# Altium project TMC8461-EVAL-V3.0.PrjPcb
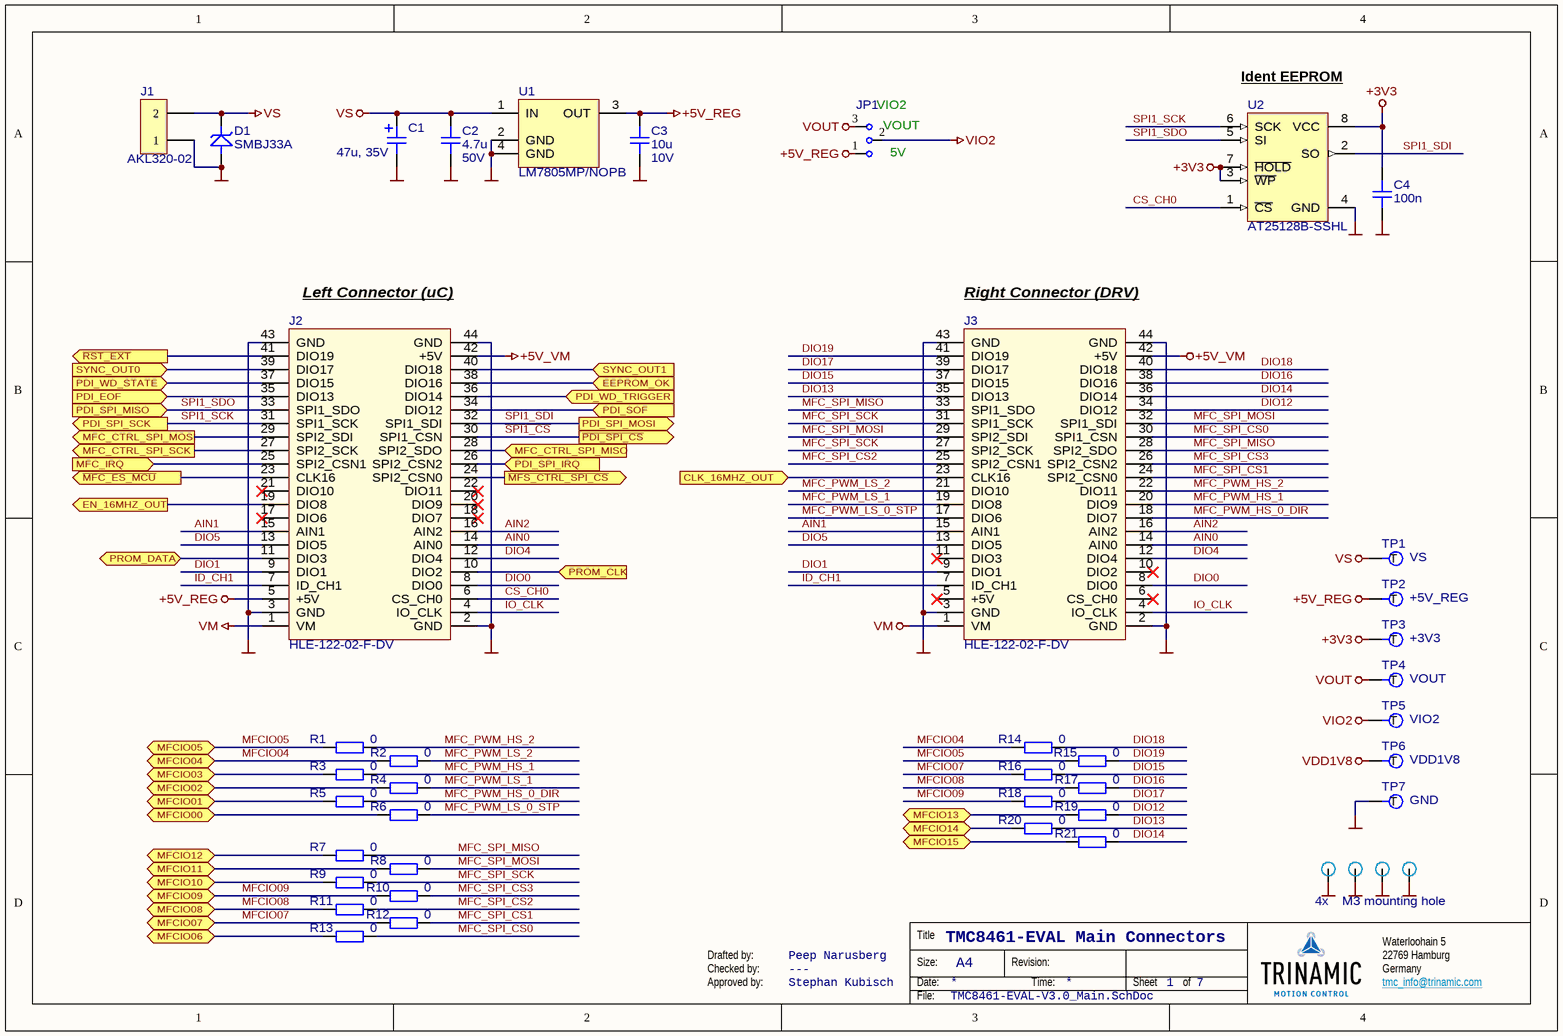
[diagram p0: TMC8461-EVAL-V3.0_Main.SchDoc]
PName: TMC8461-EVAL; PRevision: V3.0
6 sheets, 172 parts. Net scope: flat (ports and power ports of the same name join across sheets).
Board file: TMC8461-EVAL-V3.0.PcbDoc
Sheets:
  TMC8461-EVAL-V3.0_Main.SchDoc
  TMC8461-EVAL-V3.0_Power.SchDoc
  TMC8461-EVAL-V3.0_Control.SchDoc
  TMC8461-EVAL-V3.0_MFC.SchDoc
  TMC8461-EVAL-V3.0_PHY_IN.SchDoc
  TMC8461-EVAL-V3.0_PHY_OUT.SchDoc

## Sheet TMC8461-EVAL-V3.0_Main.SchDoc: Main Connectors
size A4; CompanyName: Hedgehog OÜ; Revision: V3.0; SheetNumber: 1; SheetTotal: 7; Author: Peep Narusberg; DrawnBy: Peep Narusberg; Engineer: Peep Narusberg; Organization: Hedgehog OÜ; Address1: Waterloohain 5; Address2: 22769 Hamburg; Address3: Germany; Address4: tmc_info@trinamic.com

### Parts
C1  value 47u, 35V  [CAPAE7766X63N]  (hidden comment: CAPP1)
C2  value 4.7u  Voltage: 50V  [CAPC3216N]  (hidden comment: CAPC)
C3  value 10u  Voltage: 10V  [CAPC1608N]  (hidden comment: CAPC)
C4  value 100n  [CAPC1608N]  (hidden comment: CAPC)
D1  Part Number: SMBJ33A  [DIOM4336X25N]  (hidden comment: TVS)
J1  HDR1x2A  [AKL320-02]  (value not drawn)
J2  PTC  [HLE-122-02-F-DV]  (value not drawn)
J3  PTC  [HLE-122-02-F-DV]  (value not drawn)
JP1  JUMPER1X3A  [SAMTEC_TSW-103-07-G-S]  (value not drawn)
MP1  Part Number: M3 mounting hole  [MTG3,2_6,4-VIA]  (hidden comment: MTG)  (no BOM)
MP2  MTG  [MTG3,2_6,4-VIA]  (value not drawn)  (no BOM)
MP3  MTG  [MTG3,2_6,4-VIA]  (value not drawn)  (no BOM)
MP4  MTG  [MTG3,2_6,4-VIA]  (value not drawn)  (no BOM)
R1  value 0  [RESC1005N]  (hidden comment: RESC)
R2  value 0  [RESC1005N]  (hidden comment: RESC)
R3  value 0  [RESC1005N]  (hidden comment: RESC)
R4  value 0  [RESC1005N]  (hidden comment: RESC)
R5  value 0  [RESC1005N]  (hidden comment: RESC)
R6  value 0  [RESC1005N]  (hidden comment: RESC)
R7  value 0  [RESC1005N]  (hidden comment: RESC)
R8  value 0  [RESC1005N]  (hidden comment: RESC)
R9  value 0  [RESC1005N]  (hidden comment: RESC)
R10  value 0  [RESC1005N]  (hidden comment: RESC)
R11  value 0  [RESC1005N]  (hidden comment: RESC)
R12  value 0  [RESC1005N]  (hidden comment: RESC)
R13  value 0  [RESC1005N]  (hidden comment: RESC)
R14  value 0  [RESC1005N]  (hidden comment: RESC)
R15  value 0  [RESC1005N]  (hidden comment: RESC)
R16  value 0  [RESC1005N]  (hidden comment: RESC)
R17  value 0  [RESC1005N]  (hidden comment: RESC)
R18  value 0  [RESC1005N]  (hidden comment: RESC)
R19  value 0  [RESC1005N]  (hidden comment: RESC)
R20  value 0  [RESC1005N]  (hidden comment: RESC)
R21  value 0  [RESC1005N]  (hidden comment: RESC)
TP1  VS  [TP100P254]  (no BOM)
TP2  +5V_REG  [TP100P254]  (no BOM)
TP3  +3V3  [TP100P254]  (no BOM)
TP4  VOUT  [TP100P254]  (no BOM)
TP5  VIO2  [TP100P254]  (no BOM)
TP6  VDD1V8  [TP100P254]  (no BOM)
TP7  GND  [TP100P254]  (no BOM)
U1  Part Number: LM7805MP/NOPB  [SOT230P700X180-4N-TI]  (hidden comment: LDO4-SOT223)
U2  Part Number: AT25128B-SSHL  [SOIC127P600X175-8N]

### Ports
CLK_16MHZ_OUT (in), EEPROM_OK (in), EN_16MHZ_OUT (out), MFC_CTRL_SPI_MISO (in), MFC_CTRL_SPI_MOSI (out), MFC_CTRL_SPI_SCK (out), MFC_IRQ (in), MFCIO00 (bidir), MFCIO01 (bidir), MFCIO02 (bidir), MFCIO03 (bidir), MFCIO04 (bidir), MFCIO05 (bidir), MFCIO06 (bidir), MFCIO07 (bidir), MFCIO08 (bidir), MFCIO09 (bidir), MFCIO10 (bidir), MFCIO11 (bidir), MFCIO12 (bidir), MFCIO13 (bidir), MFCIO14 (bidir), MFCIO15 (bidir), PDI_EOF (in), PDI_SOF (in), PDI_SPI_IRQ (in), PDI_SPI_MISO (in), PDI_SPI_MOSI (out), PDI_SPI_SCK (out), PDI_WD_STATE (in), PDI_WD_TRIGGER (in), PROM_CLK (in), PROM_DATA (bidir), SYNC_OUT0 (in), SYNC_OUT1 (in), ~{MFC_ES_MCU} (out), ~{MFS_CTRL_SPI_CS} (out), ~{PDI_SPI_CS} (out), ~{RST_EXT} (out)

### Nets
+3V3: C4.2 TP3.1(T) U2.3(~{WP}) U2.7(~{HOLD}) U2.8(VCC)
+5V_REG: C3.2 J2.5(+5V) JP1.1(C1) TP2.1(T) U1.3(OUT)
+5V_VM: J2.42(+5V) J3.42(+5V)
GND: C1.2(-) C2.1 C3.1 C4.1 D1.2(A) J1.1 J2.2(GND) J2.3(GND) J2.43(GND) J2.44(GND) J3.2(GND) J3.3(GND) J3.43(GND) J3.44(GND) MP1.1(GND) MP2.1(GND) MP3.1(GND) MP4.1(GND) TP7.1(T) U1.2(GND) U1.4(GND) U2.4(GND)
VDD1V8: TP6.1(T)
VIO2: JP1.2(C2) TP5.1(T)
VM: J2.1(VM) J3.1(VM)
VOUT: JP1.3(C3) TP4.1(T)
VS: C1.1(+) C2.2 D1.1(K) J1.2 TP1.1(T) U1.1(IN)
~{SPI1_CS}: J2.30(SPI1_CSN) ; port ~{PDI_SPI_CS}
AIN0: J2.14(AIN0) J3.14(AIN0)
AIN1: J2.15(AIN1) J3.15(AIN1)
AIN2: J2.16(AIN2) J3.16(AIN2)
CLK_16MHZ_OUT: J3.23(CLK16) ; port CLK_16MHZ_OUT
CS_CH0: J2.6(CS_CH0) U2.1(~{CS})
DIO0: J2.8(DIO0) J3.8(DIO0)
DIO1: J2.9(DIO1) J3.9(DIO1)
DIO4: J2.12(DIO4) J3.12(DIO4)
DIO5: J2.13(DIO5) J3.13(DIO5)
DIO12: J3.34(DIO12) R19.2
DIO13: J3.35(DIO13) R20.2
DIO14: J3.36(DIO14) R21.2
DIO15: J3.37(DIO15) R16.2
DIO16: J3.38(DIO16) R17.2
DIO17: J3.39(DIO17) R18.2
DIO18: J3.40(DIO18) R14.2
DIO19: J3.41(DIO19) R15.2
EEPROM_OK: J2.38(DIO16) ; port EEPROM_OK
EN_16MHZ_OUT: J2.19(DIO8) ; port EN_16MHZ_OUT
ID_CH1: J2.7(ID_CH1) J3.7(ID_CH1)
IO_CLK: J2.4(IO_CLK) J3.4(IO_CLK)
~{MFC_ES_MCU}: J2.23(CLK16) ; port ~{MFC_ES_MCU}
~{MFS_CTRL_SPI_CS}: J2.24(SPI2_CSN0) ; port ~{MFS_CTRL_SPI_CS}
MFC_CTRL_SPI_MISO: J2.28(SPI2_SDO) ; port MFC_CTRL_SPI_MISO
MFC_CTRL_SPI_MOSI: J2.29(SPI2_SDI) ; port MFC_CTRL_SPI_MOSI
MFC_CTRL_SPI_SCK: J2.27(SPI2_SCK) ; port MFC_CTRL_SPI_SCK
MFC_IRQ: J2.25(SPI2_CSN1) ; port MFC_IRQ
MFC_PWM_HS_0_DIR: J3.18(DIO7) R5.2
MFC_PWM_HS_1: J3.20(DIO9) R3.2
MFC_PWM_HS_2: J3.22(DIO11) R1.2
MFC_PWM_LS_0_STP: J3.17(DIO6) R6.2
MFC_PWM_LS_1: J3.19(DIO8) R4.2
MFC_PWM_LS_2: J3.21(DIO10) R2.2
MFC_SPI_CS0: J3.30(SPI1_CSN) R13.2
MFC_SPI_CS1: J3.24(SPI2_CSN0) R12.2
MFC_SPI_CS2: J3.25(SPI2_CSN1) R11.2
MFC_SPI_CS3: J3.26(SPI2_CSN2) R10.2
MFC_SPI_MISO: J3.28(SPI2_SDO) J3.33(SPI1_SDO) R7.2
MFC_SPI_MOSI: J3.29(SPI2_SDI) J3.32(SPI1_SDI) R8.2
MFC_SPI_SCK: J3.27(SPI2_SCK) J3.31(SPI1_SCK) R9.2
MFCIO00: R6.1 ; port MFCIO00
MFCIO01: R5.1 ; port MFCIO01
MFCIO02: R4.1 ; port MFCIO02
MFCIO03: R3.1 ; port MFCIO03
MFCIO04: R2.1 R14.1 ; port MFCIO04
MFCIO05: R1.1 R15.1 ; port MFCIO05
MFCIO06: R13.1 ; port MFCIO06
MFCIO07: R12.1 R16.1 ; port MFCIO07
MFCIO08: R11.1 R17.1 ; port MFCIO08
MFCIO09: R10.1 R18.1 ; port MFCIO09
MFCIO10: R9.1 ; port MFCIO10
MFCIO11: R8.1 ; port MFCIO11
MFCIO12: R7.1 ; port MFCIO12
MFCIO13: R19.1 ; port MFCIO13
MFCIO14: R20.1 ; port MFCIO14
MFCIO15: R21.1 ; port MFCIO15
PDI_EOF: J2.35(DIO13) ; port PDI_EOF
PDI_SOF: J2.34(DIO12) ; port PDI_SOF
PDI_SPI_IRQ: J2.26(SPI2_CSN2) ; port PDI_SPI_IRQ
PDI_WD_STATE: J2.37(DIO15) ; port PDI_WD_STATE
PDI_WD_TRIGGER: J2.36(DIO14) ; port PDI_WD_TRIGGER
PROM_CLK: J2.10(DIO2) ; port PROM_CLK
PROM_DATA: J2.11(DIO3) ; port PROM_DATA
~{RST_EXT}: J2.41(DIO19) ; port ~{RST_EXT}
SPI1_SCK: J2.31(SPI1_SCK) U2.6(SCK) ; port PDI_SPI_SCK
SPI1_SDI: J2.32(SPI1_SDI) U2.2(SO) ; port PDI_SPI_MOSI
SPI1_SDO: J2.33(SPI1_SDO) U2.5(SI) ; port PDI_SPI_MISO
SYNC_OUT0: J2.39(DIO17) ; port SYNC_OUT0
SYNC_OUT1: J2.40(DIO18) ; port SYNC_OUT1

Not connected (* = marked no-connect by the designer): J2 17(DIO6)* 18(DIO7)* 20(DIO9)* 21(DIO10)* 22(DIO11)*; J3 5(+5V)* 6(CS_CH0)* 10(DIO2)* 11(DIO3)*

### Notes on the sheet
- (near JP1) VIO2
- (near U2) Ident EEPROM
- (near JP1) VOUT
- (near JP1) 5V
- (near J2) Left Connector (uC)
- (near J3) Right Connector (DRV)
- 4x
- Drafted by:
- Checked by:
- Approved by:
- Peep Narusberg
- ---
- Stephan Kubisch

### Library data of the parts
C1 = 50571: Polarized capacitor, pin1 pos; Part Number: UWT1V470MCL1GS; Manufacturer: Nichicon; Id: 50571; Type: CAP
C2 = 20078: Ceramic chip capacitor; Manufacturer: Any; Part Number: 4.7u, 50V, X5R, 1206 (3216 metric) chip capacitor; Id: 20078
C3 = 20111: Ceramic chip capacitor; Manufacturer: Any; Part Number: 10u, 10V, X5R, 0603 (1608 metric) chip capacitor; Id: 20111
C4 = 20027: Ceramic chip capacitor; Manufacturer: Any; Part Number: 100n, 50V, X5R, 0603 (1608 metric) chip capacitor; Id: 20027; Voltage: 50V
D1 = 50555: TVS, Pin1 Cathode; Manufacturer: ST; Id: 50555; Value: 33V,600W
J1 = 50537: 1X2 pin connector; Manufacturer: Metz Connect; Id: 50537; Value: 2 pin
J2 J3 = 50289: Trinamic 44-pin connector; Manufacturer: Samtec; Id: 50289; Value: 44pin
JP1 = 50570: Jumper pin header; Part Number: TSW-103-07-G-S; Manufacturer: Samtec; Id: 50570
MP1 = 50193: Mounting hole; Id: 50193; Value: 3.2x6.4 VIA
MP2-MP4 = 50193: Mounting hole; Part Number: M3 mounting hole; Id: 50193; Value: 3.2x6.4 VIA
R1-R21 = 10052: Chip Resistor; Manufacturer: Any; Part Number: 0, -, -, 0402 (1005 metric) chip resistor; Id: 10052
TP1-TP7 = 50094: Round testpoint; Id: 50094; Value: c160 (P100 probe)
U1 = 50548: LDO in SOT223 package; Manufacturer: Texas Instruments; Id: 50548; Value: 5V 1A
U2 = 50499: SPI Serial Flash Memory; Manufacturer: Atmel; Id: 50499; Value: 128Kb

## Sheet TMC8461-EVAL-V3.0_Power.SchDoc: Power Supply
size A4; CompanyName: Hedgehog OÜ; Revision: V3.0; SheetNumber: 2; SheetTotal: 7; Author: Peep Narusberg; DrawnBy: Peep Narusberg; Engineer: Peep Narusberg; Organization: Hedgehog OÜ; Address1: Waterloohain 5; Address2: 22769 Hamburg; Address3: Germany; Address4: tmc_info@trinamic.com
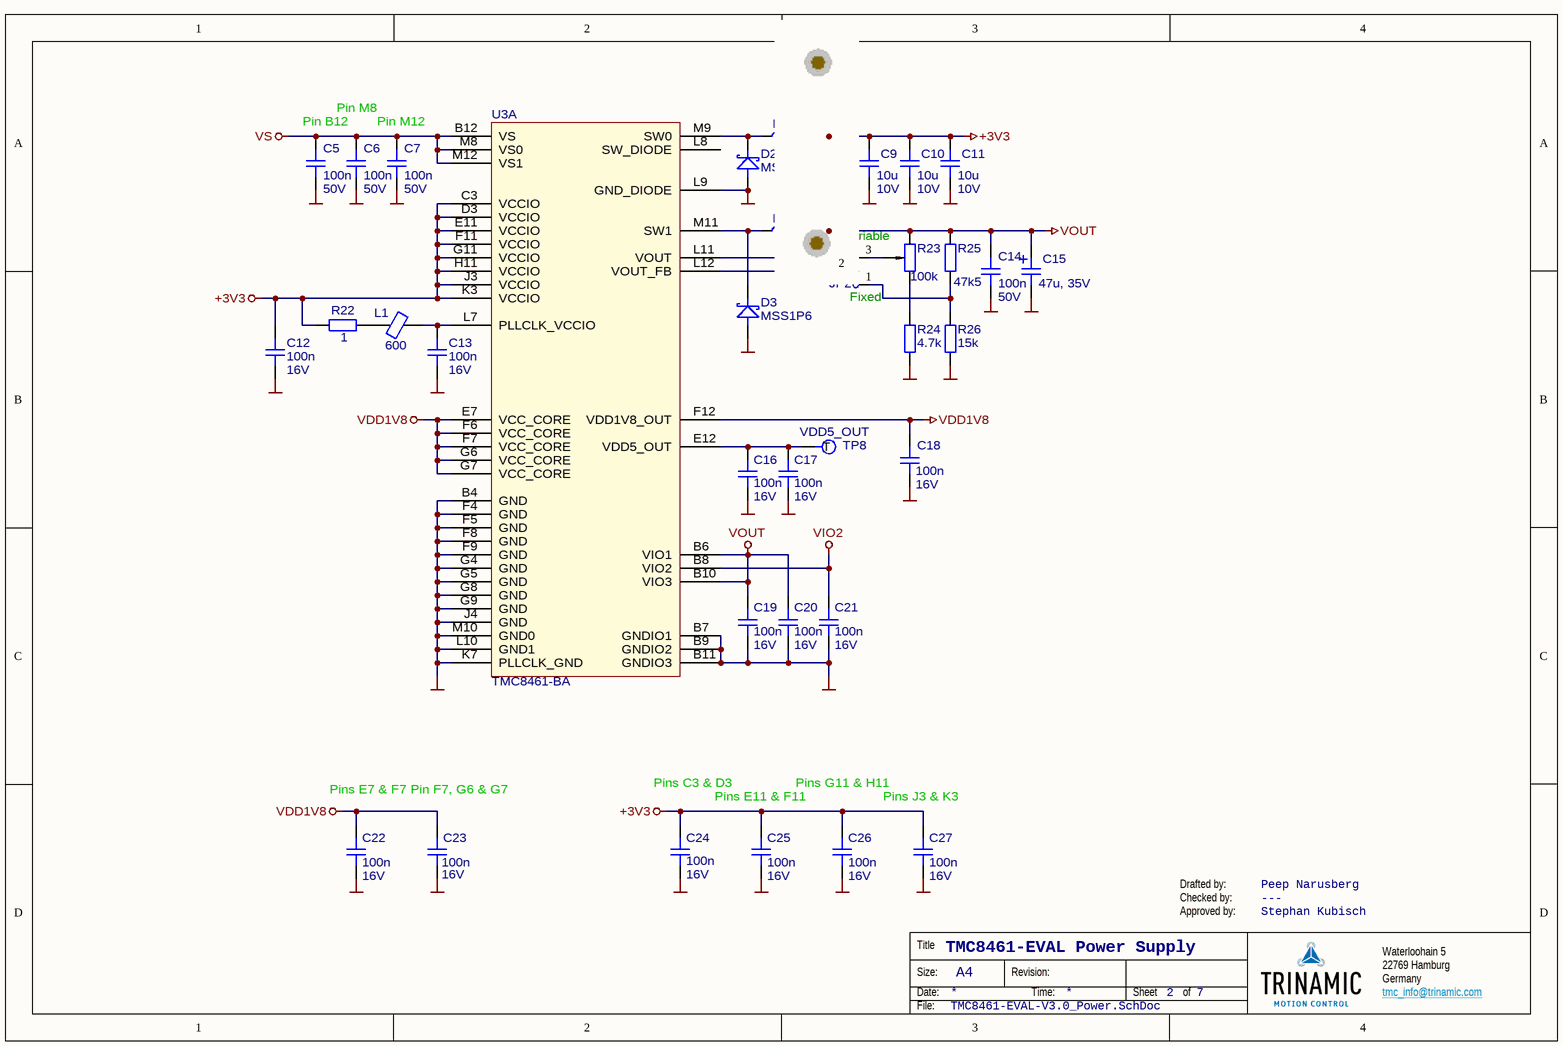
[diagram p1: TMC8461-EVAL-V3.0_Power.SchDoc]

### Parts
C5  value 100n  Voltage: 50V  [CAPC1608N]  (hidden comment: CAPC)
C6  value 100n  Voltage: 50V  [CAPC1608N]  (hidden comment: CAPC)
C7  value 100n  Voltage: 50V  [CAPC1608N]  (hidden comment: CAPC)
C8  value 10u  Voltage: 10V  [CAPC1608N]  (hidden comment: CAPC)
C9  value 10u  Voltage: 10V  [CAPC1608N]  (hidden comment: CAPC)
C10  value 10u  Voltage: 10V  [CAPC1608N]  (hidden comment: CAPC)
C11  value 10u  Voltage: 10V  [CAPC1608N]  (hidden comment: CAPC)
C12  value 100n  Voltage: 16V  [CAPC1005N]  (hidden comment: CAPC)
C13  value 100n  Voltage: 16V  [CAPC1005N]  (hidden comment: CAPC)
C14  value 100n  Voltage: 50V  [CAPC1608N]  (hidden comment: CAPC)
C15  value 47u, 35V  [CAPAE7766X63N]  (hidden comment: CAPP1)
C16  value 100n  Voltage: 16V  [CAPC1005N]  (hidden comment: CAPC)
C17  value 100n  Voltage: 16V  [CAPC1005N]  (hidden comment: CAPC)
C18  value 100n  Voltage: 16V  [CAPC1005N]  (hidden comment: CAPC)
C19  value 100n  Voltage: 16V  [CAPC1005N]  (hidden comment: CAPC)
C20  value 100n  Voltage: 16V  [CAPC1005N]  (hidden comment: CAPC)
C21  value 100n  Voltage: 16V  [CAPC1005N]  (hidden comment: CAPC)
C22  value 100n  Voltage: 16V  [CAPC1005N]  (hidden comment: CAPC)
C23  value 100n  Voltage: 16V  [CAPC1005N]  (hidden comment: CAPC)
C24  value 100n  Voltage: 16V  [CAPC1005N]  (hidden comment: CAPC)
C25  value 100n  Voltage: 16V  [CAPC1005N]  (hidden comment: CAPC)
C26  value 100n  Voltage: 16V  [CAPC1005N]  (hidden comment: CAPC)
C27  value 100n  Voltage: 16V  [CAPC1005N]  (hidden comment: CAPC)
D2  Part Number: MSS1P6  [SODFL250130X73N]  (hidden comment: DIO-SCHOTTKY)
D3  Part Number: MSS1P6  [SODFL250130X73N]  (hidden comment: DIO-SCHOTTKY)
JP2  JUMPER1X3A  [SAMTEC_TSW-103-07-G-S]  (value not drawn)
L1  value 600  [INDC1608X09N]  (hidden comment: FB)
L2  value 68u  [WE-744042680]  (hidden comment: INDM)
L3  value 68u  [WE-744042680]  (hidden comment: INDM)
R22  value 1  [RESC1608N]  (hidden comment: RESC)
R23  value 100k  [VISHAY_T93YA]  (hidden comment: VRES)
R24  value 4.7k  [RESC1608N]  (hidden comment: RESC)
R25  value 47k5  [RESC1608N]  (hidden comment: RESC)
R26  value 15k  [RESC1608N]  (hidden comment: RESC)
TP8  VDD5_OUT  [TP100P254]  (no BOM)
U3  50588  [BGA144C80P12X12_1000X1000X100]  (value not drawn)  (part A of 6)

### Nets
+3V3: C8.2 C9.2 C10.2 C11.2 C12.2 C24.2 C25.2 C26.2 C27.2 L2.2 R22.1 U3.C3(VCCIO) U3.D3(VCCIO) U3.E11(VCCIO) U3.F11(VCCIO) U3.G11(VCCIO) U3.H11(VCCIO) U3.J3(VCCIO) U3.K3(VCCIO)
GND: C5.1 C6.1 C7.1 C8.1 C9.1 C10.1 C11.1 C12.1 C13.1 C14.1 C15.2(-) C16.1 C17.1 C18.1 C19.1 C20.1 C21.1 C22.1 C23.1 C24.1 C25.1 C26.1 C27.1 D2.2 D3.2 R24.1 R26.1 U3.B4(GND) U3.B7(GNDIO1) U3.B9(GNDIO2) U3.B11(GNDIO3) U3.F4(GND) U3.F5(GND) U3.F8(GND) U3.F9(GND) U3.G4(GND) U3.G5(GND) U3.G8(GND) U3.G9(GND) U3.J4(GND) U3.K7(PLLCLK_GND) U3.L9(GND_DIODE) U3.L10(GND1) U3.M10(GND0)
VDD1V8: C18.2 C22.2 C23.2 U3.E7(VCC_CORE) U3.F6(VCC_CORE) U3.F7(VCC_CORE) U3.F12(VDD1V8_OUT) U3.G6(VCC_CORE) U3.G7(VCC_CORE)
VIO2: C21.2 U3.B8(VIO2)
VOUT: C14.2 C15.1(+) C19.2 C20.2 L3.2 R23.3 R25.2 U3.B6(VIO1) U3.B10(VIO3) U3.L11(VOUT)
VS: C5.2 C6.2 C7.2 U3.B12(VS) U3.M8(VS0) U3.M12(VS1)
NetC13_2: C13.2 L1.2 U3.L7(PLLCLK_VCCIO)
NetC16_2: C16.2 C17.2 TP8.1(T) U3.E12(VDD5_OUT)
NetD2_1: D2.1 L2.1 U3.M9(SW0)
NetD3_1: D3.1 L3.1 U3.M11(SW1)
NetJP2_1: JP2.1(C1) R25.1 R26.2
NetJP2_2: JP2.2(C2) U3.L12(VOUT_FB)
NetJP2_3: JP2.3(C3) R23.2
NetL1_1: L1.1 R22.2
NetR23_1: R23.1 R24.2

Not connected (* = marked no-connect by the designer): U3 L8(SW_DIODE)

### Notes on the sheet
- Pin B12
- Pin M8
- Pin M12
- (near R23) Variable
- VOUT
- (near JP2) Fixed
- Pins E7 & F7
- (near C23) Pin F7, G6 & G7
- Pins C3 & D3
- Pins E11 & F11
- Pins G11 & H11
- Pins J3 & K3
- Drafted by:
- Checked by:
- Approved by:
- Peep Narusberg
- ---
- Stephan Kubisch

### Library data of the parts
C5-C7 C14 = 20027: Ceramic chip capacitor; Manufacturer: Any; Part Number: 100n, 50V, X5R, 0603 (1608 metric) chip capacitor; Id: 20027
C8-C11 = 20111: as C3 on sheet TMC8461-EVAL-V3.0_Main
C12 C13 C16-C27 = 20000: Ceramic chip capacitor; Manufacturer: Any; Part Number: 100n, 16V, X5R, 0402 (1005 metric) chip capacitor; Id: 20000
C15 = 50571: as C1 on sheet TMC8461-EVAL-V3.0_Main
D2 D3 = 50568: Schottky Diode, pin1 cathode; Manufacturer: Vishay; Id: 50568; Value: 1A, 60V
JP2 = 50570: as JP1 on sheet TMC8461-EVAL-V3.0_Main
L1 = 60036: Ferrite bead; Manufacturer: Wuerth; Part Number: 742792651; Id: 60036; Tolerance: 25; Current: 1A
L2 L3 = 60034: Molded inductor; Manufacturer: Wuerth; Part Number: 744042680; Id: 60034; Tolerance: 30; Current: 0.5A
R22 = 10031: Chip Resistor; Manufacturer: Any; Part Number: 1, 1%, 100mW, 0603 (1608 metric) chip resistor; Id: 10031; Power: 100mW; Tolerance: 1%
R23 = 50569: Trimmer potentiometer; Part Number: T93YA104KT20; Manufacturer: Vishay; Id: 50569
R24 = 10032: Chip Resistor; Manufacturer: Any; Part Number: 4.7k, 1%, 100mW, 0603 (1608 metric) chip resistor; Id: 10032; Power: 100mW; Tolerance: 1%
R25 = 10164: Chip Resistor; Manufacturer: Any; Part Number: 47k5, 1%, 100mW, 0603 (1608 metric) chip resistor; Id: 10164; Power: 100mW; Tolerance: 1%
R26 = 10050: Chip Resistor; Manufacturer: Any; Part Number: 15k, 1%, 100mW, 0603 (1608 metric) chip resistor; Id: 10050; Power: 100mW; Tolerance: 1%
TP8 = 50094: as TP1 on sheet TMC8461-EVAL-V3.0_Main
U3 = 50588: Integrated EtherCAT Slave Controller; Manufacturer: Trinamic; Value: EthCat

## Sheet TMC8461-EVAL-V3.0_Control.SchDoc: PDI IOs to/from MCU
size A4; CompanyName: Hedgehog OÜ; Revision: V3.0; SheetNumber: 3; SheetTotal: 7; Author: Peep Narusberg; DrawnBy: Peep Narusberg; Engineer: Peep Narusberg; Organization: Hedgehog OÜ; Address1: Waterloohain 5; Address2: 22769 Hamburg; Address3: Germany; Address4: tmc_info@trinamic.com
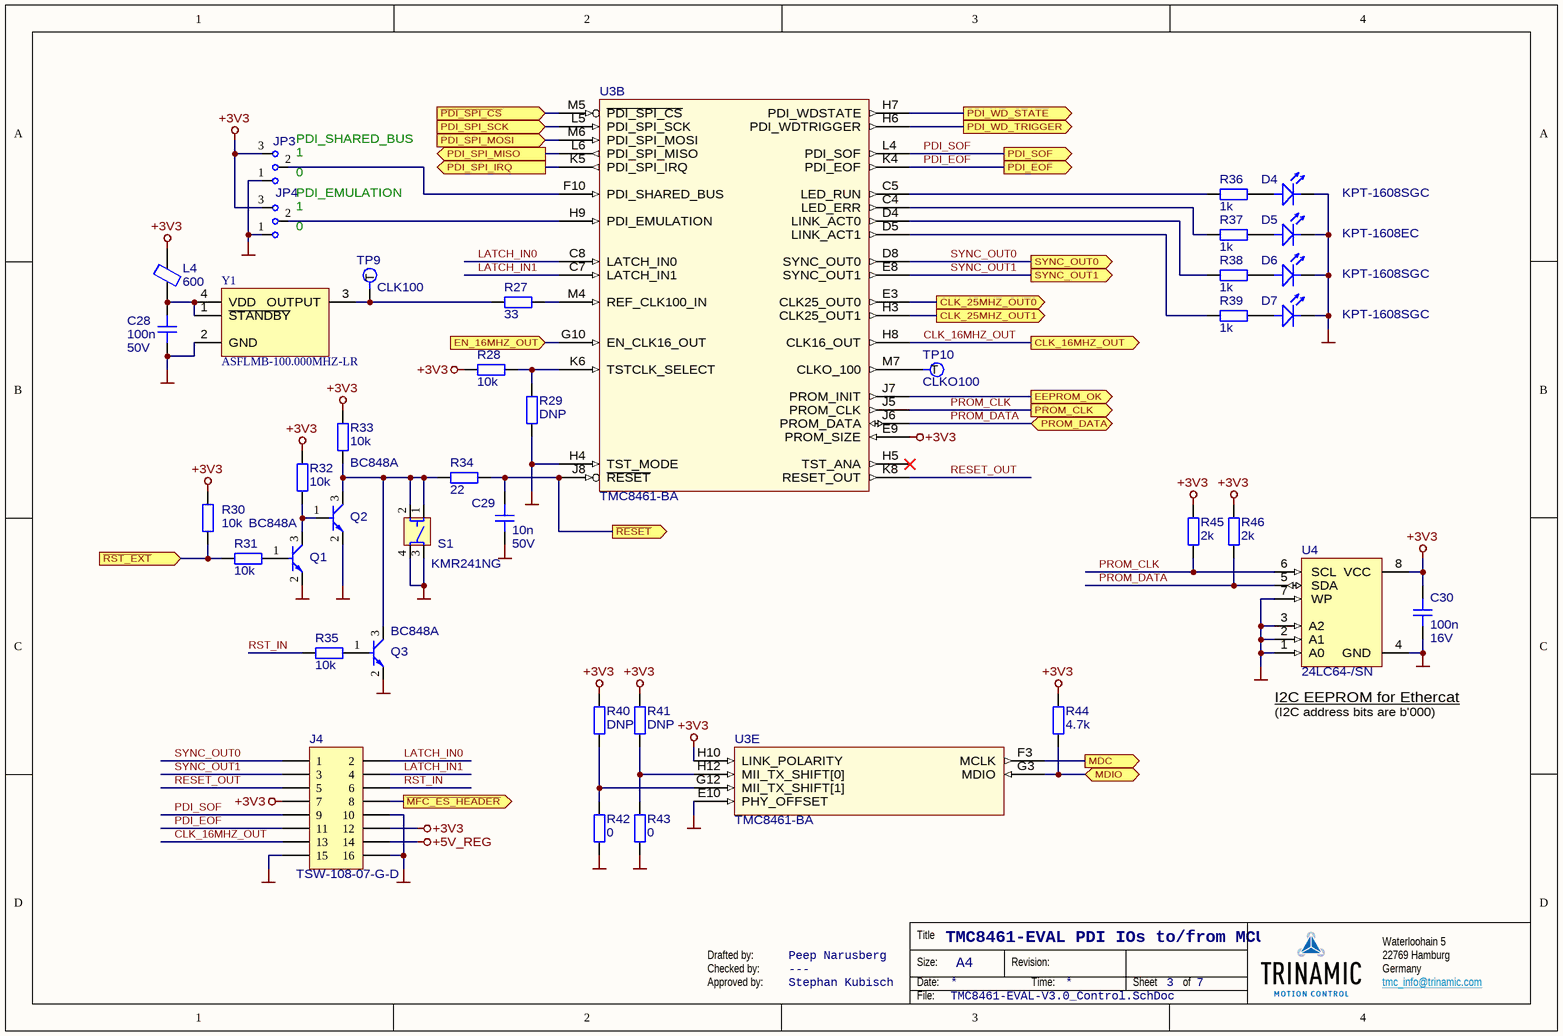
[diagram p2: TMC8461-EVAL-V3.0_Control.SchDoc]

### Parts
C28  value 100n  Voltage: 50V  [CAPC1608N]  (hidden comment: CAPC)
C29  value 10n  Voltage: 50V  [CAPC1608N]  (hidden comment: CAPC)
C30  value 100n  Voltage: 16V  [CAPC1005N]  (hidden comment: CAPC)
D4  Part Number: KPT-1608SGC  [LED-KPT1608G-MFG]  (hidden comment: DIO-LED)
D5  Part Number: KPT-1608EC  [LED-KPT1608R-MFG]  (hidden comment: DIO-LED)
D6  Part Number: KPT-1608SGC  [LED-KPT1608G-MFG]  (hidden comment: DIO-LED)
D7  Part Number: KPT-1608SGC  [LED-KPT1608G-MFG]  (hidden comment: DIO-LED)
J4  Part Number: TSW-108-07-G-D  [SAMTEC_TSW-108-07-G-D]  (hidden comment: HDR2x8)
JP3  JUMPER1X3A  [SAMTEC_TSW-103-07-G-S]  (value not drawn)
JP4  JUMPER1X3A  [SAMTEC_TSW-103-07-G-S]  (value not drawn)
L4  value 600  [INDC1608X09N]  (hidden comment: FB)
Q1  Part Number: BC848A  [SOT95P280X130-3N]  (hidden comment: BJT-NPN1)
Q2  Part Number: BC848A  [SOT95P280X130-3N]  (hidden comment: BJT-NPN1)
Q3  Part Number: BC848A  [SOT95P280X130-3N]  (hidden comment: BJT-NPN1)
R27  value 33  [RESC1608N]  (hidden comment: RESC)
R28  value 10k  [RESC1608N]  (hidden comment: RESC)
R29  value DNP  [RESC1608N]  (hidden comment: RESC)
R30  value 10k  [RESC1608N]  (hidden comment: RESC)
R31  value 10k  [RESC1608N]  (hidden comment: RESC)
R32  value 10k  [RESC1608N]  (hidden comment: RESC)
R33  value 10k  [RESC1608N]  (hidden comment: RESC)
R34  value 22  [RESC1608N]  (hidden comment: RESC)
R35  value 10k  [RESC1608N]  (hidden comment: RESC)
R36  value 1k  [RESC1608N]  (hidden comment: RESC)
R37  value 1k  [RESC1608N]  (hidden comment: RESC)
R38  value 1k  [RESC1608N]  (hidden comment: RESC)
R39  value 1k  [RESC1608N]  (hidden comment: RESC)
R40  value DNP  [RESC1608N]  (hidden comment: RESC)
R41  value DNP  [RESC1608N]  (hidden comment: RESC)
R42  value 0  [RESC1608N]  (hidden comment: RESC)
R43  value 0  [RESC1608N]  (hidden comment: RESC)
R44  value 4.7k  [RESC1608N]  (hidden comment: RESC)
R45  value 2k  [RESC1608N]  (hidden comment: RESC)
R46  value 2k  [RESC1608N]  (hidden comment: RESC)
S1  Part Number: KMR241NG  [CK-KMR2]  (hidden comment: SW_4PIN)
TP9  CLK100  [TP100P254]  (no BOM)
TP10  CLKO100  [TP100P254]  (no BOM)
U3  50588  [BGA144C80P12X12_1000X1000X100]  (value not drawn)  (parts B,E of 6)
U4  Part Number: 24LC64-/SN  [SOIC127P600X175-8N]  (hidden comment: 24LC64)
Y1  Part Number: ASFLMB-100.000MHZ-LR  [OSC500X320X85N]  (hidden comment: OSC-ASFLMB)

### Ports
CLK_16MHZ_OUT (out), CLK_25MHZ_OUT0 (out), CLK_25MHZ_OUT1 (out), EEPROM_OK (out), EN_16MHZ_OUT (in), MDC (out), MDIO (bidir), PDI_EOF (out), PDI_SOF (out), PDI_SPI_IRQ (out), PDI_SPI_MISO (out), PDI_SPI_MOSI (in), PDI_SPI_SCK (in), PDI_WD_STATE (out), PDI_WD_TRIGGER (out), PROM_CLK (out), PROM_DATA (bidir), SYNC_OUT0 (out), SYNC_OUT1 (out), ~{MFC_ES_HEADER} (out), ~{PDI_SPI_CS} (in), ~{RESET} (out), ~{RST_EXT} (in)

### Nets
+3V3: C30.2 J4.7 J4.12 JP3.3(C3) JP4.3(C3) L4.2 R28.2 R30.1 R32.2 R33.2 R40.2 R41.2 R44.2 R45.2 R46.2 U3.E9(PROM_SIZE) U3.H10(LINK_POLARITY) U4.8(VCC)
+5V_REG: J4.14
GND: C28.1 C29.1 C30.1 D4.1 D5.1 D6.1 D7.1 J4.10 J4.15 J4.16 JP3.1(C1) JP4.1(C1) Q1.2(E) Q2.2(E) Q3.2(E) R29.1 R42.1 R43.1 S1.3 S1.4 U3.E10(PHY_OFFSET) U3.H4(TST_MODE) U4.1(A0) U4.2(A1) U4.3(A2) U4.4(GND) U4.7(WP) Y1.2(GND)
~{SPI1_CS}: U3.M5(~{PDI_SPI_CS}) ; port ~{PDI_SPI_CS}
CLK_16MHZ_OUT: J4.13 U3.H8(CLK16_OUT) ; port CLK_16MHZ_OUT
CLK_25MHZ_OUT0: U3.E3(CLK25_OUT0) ; port CLK_25MHZ_OUT0
CLK_25MHZ_OUT1: U3.H3(CLK25_OUT1) ; port CLK_25MHZ_OUT1
EEPROM_OK: U3.J7(PROM_INIT) ; port EEPROM_OK
EN_16MHZ_OUT: U3.G10(EN_CLK16_OUT) ; port EN_16MHZ_OUT
LATCH_IN0: J4.2 U3.C8(LATCH_IN0)
LATCH_IN1: J4.4 U3.C7(LATCH_IN1)
~{MFC_ES_HEADER}: J4.8 ; port ~{MFC_ES_HEADER}
MDC: U3.F3(MCLK) ; port MDC
MDIO: R44.1 U3.G3(MDIO) ; port MDIO
PDI_EOF: J4.11 U3.K4(PDI_EOF) ; port PDI_EOF
PDI_SOF: J4.9 U3.L4(PDI_SOF) ; port PDI_SOF
PDI_SPI_IRQ: U3.K5(PDI_SPI_IRQ) ; port PDI_SPI_IRQ
PDI_WD_STATE: U3.H7(PDI_WDSTATE) ; port PDI_WD_STATE
PDI_WD_TRIGGER: U3.H6(PDI_WDTRIGGER) ; port PDI_WD_TRIGGER
PROM_CLK: R45.1 U3.J5(PROM_CLK) U4.6(SCL) ; port PROM_CLK
PROM_DATA: R46.1 U3.J6(PROM_DATA) U4.5(SDA) ; port PROM_DATA
~{RESET}: C29.2 R34.2 U3.J8(~{RESET}) ; port ~{RESET}
~{RST_EXT}: R30.2 R31.2 ; port ~{RST_EXT}
RESET_OUT: J4.5 U3.K8(RESET_OUT)
RST_IN: J4.6 R35.2
SPI1_SCK: U3.L5(PDI_SPI_SCK) ; port PDI_SPI_SCK
SPI1_SDI: U3.M6(PDI_SPI_MOSI) ; port PDI_SPI_MOSI
SPI1_SDO: U3.L6(PDI_SPI_MISO) ; port PDI_SPI_MISO
SYNC_OUT0: J4.1 U3.D8(SYNC_OUT0) ; port SYNC_OUT0
SYNC_OUT1: J4.3 U3.E8(SYNC_OUT1) ; port SYNC_OUT1
NetC28_2: C28.2 L4.1 Y1.1(~{STANDBY}) Y1.4(VDD)
NetD4_2: D4.2 R36.2
NetD5_2: D5.2 R37.2
NetD6_2: D6.2 R38.2
NetD7_2: D7.2 R39.2
NetJP3_2: JP3.2(C2) U3.F10(PDI_SHARED_BUS)
NetJP4_2: JP4.2(C2) U3.H9(PDI_EMULATION)
NetQ1_1: Q1.1(B) R31.1
NetQ1_3: Q1.3(C) Q2.1(B) R32.1
NetQ2_3: Q2.3(C) Q3.3(C) R33.1 R34.1 S1.1 S1.2
NetQ3_1: Q3.1(B) R35.1
NetR27_1: R27.1 TP9.1(T) Y1.3(OUTPUT)
NetR27_2: R27.2 U3.M4(REF_CLK100_IN)
NetR28_1: R28.1 R29.2 U3.K6(TSTCLK_SELECT)
NetR36_1: R36.1 U3.C5(LED_RUN)
NetR37_1: R37.1 U3.C4(LED_ERR)
NetR38_1: R38.1 U3.D4(LINK_ACT0)
NetR39_1: R39.1 U3.D5(LINK_ACT1)
NetR40_1: R40.1 R42.2 U3.G12(MII_TX_SHIFT[1])
NetR41_1: R41.1 R43.2 U3.H12(MII_TX_SHIFT[0])
NetTP10_1: TP10.1(T) U3.M7(CLKO_100)

Not connected (* = marked no-connect by the designer): U3 H5(TST_ANA)*

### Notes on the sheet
- (near JP3) PDI_SHARED_BUS
- (near JP3) 1
- (near JP3) 0
- PDI_EMULATION
- 1
- (near JP4) 0
- (near U4) I2C EEPROM for Ethercat
- (I2C address bits are b'000)
- Drafted by:
- Checked by:
- Approved by:
- Peep Narusberg
- ---
- Stephan Kubisch

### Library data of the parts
C28 = 20027: as C5 on sheet TMC8461-EVAL-V3.0_Power
C29 = 20038: Ceramic chip capacitor; Manufacturer: Any; Part Number: 10n, 50V, X5R, 0603 (1608 metric) chip capacitor; Id: 20038
C30 = 20000: as C12 on sheet TMC8461-EVAL-V3.0_Power
D4 D6 D7 = 50005: LED, pin 1 cathode; Manufacturer: Kingbright; Id: 50005; Value: SB Green
D5 = 50002: LED, pin 1 cathode; Manufacturer: Kingbright; Id: 50002; Value: HE Red
J4 = 50576: 2x8 pin connector; Manufacturer: Samtec; Id: 50576
JP3 JP4 = 50570: as JP1 on sheet TMC8461-EVAL-V3.0_Main
L4 = 60036: as L1 on sheet TMC8461-EVAL-V3.0_Power
Q1-Q3 = 50574: NPN BJT in 3-pin package, 1B 2E 3C; Manufacturer: Diodes Inc; Id: 50574; Value: 30V 100mA
R27 = 10170: Chip Resistor; Manufacturer: Any; Part Number: 33, 1%, 100mW, 0603 (1608 metric) chip resistor; Id: 10170; Power: 100mW; Tolerance: 1%
R28 R30-R33 R35 = 10028: Chip Resistor; Manufacturer: Any; Part Number: 10k, 1%, 100mW, 0603 (1608 metric) chip resistor; Id: 10028; Power: 100mW; Tolerance: 1%
R29 R40 R41 = 40007: Chip Resistor; Id: 40007
R34 = 10034: Chip Resistor; Manufacturer: Any; Part Number: 22, 1%, 100mW, 0603 (1608 metric) chip resistor; Id: 10034; Power: 100mW; Tolerance: 1%
R36-R39 = 10049: Chip Resistor; Manufacturer: Any; Part Number: 1k, 1%, 100mW, 0603 (1608 metric) chip resistor; Id: 10049; Power: 100mW; Tolerance: 1%
R42 R43 = 10054: Chip Resistor; Manufacturer: Any; Part Number: 0, -, -, 0603 (1608 metric) chip resistor; Id: 10054
R44 = 10032: as R24 on sheet TMC8461-EVAL-V3.0_Power
R45 R46 = 10165: Chip Resistor; Manufacturer: Any; Part Number: 2k, 1%, 100mW, 0603 (1608 metric) chip resistor; Id: 10165; Power: 100mW; Tolerance: 1%
S1 = 50573: Switch, 4 pin; Manufacturer: C&K; Id: 50573
TP9 TP10 = 50094: as TP1 on sheet TMC8461-EVAL-V3.0_Main
U3 = 50588: as U3 on sheet TMC8461-EVAL-V3.0_Power
U4 = 50577: I2C serial EEPROM in 8 pin case; Manufacturer: Microchip; Id: 50577; Value: 64KB
Y1 = 50639: Standard Clock Oscillators 100MHz 3.3Volts 25ppm -40C +85C 15pF; Manufacturer: Abracon; Id: 50639; Value: 100M

## Sheet TMC8461-EVAL-V3.0_MFC.SchDoc: MFC
size A4; CompanyName: Hedgehog OÜ; Revision: V3.0; SheetNumber: 4; SheetTotal: 7; Author: Peep Narusberg; DrawnBy: Peep Narusberg; Engineer: Peep Narusberg; Organization: Hedgehog OÜ; Address1: Waterloohain 5; Address2: 22769 Hamburg; Address3: Germany; Address4: tmc_info@trinamic.com
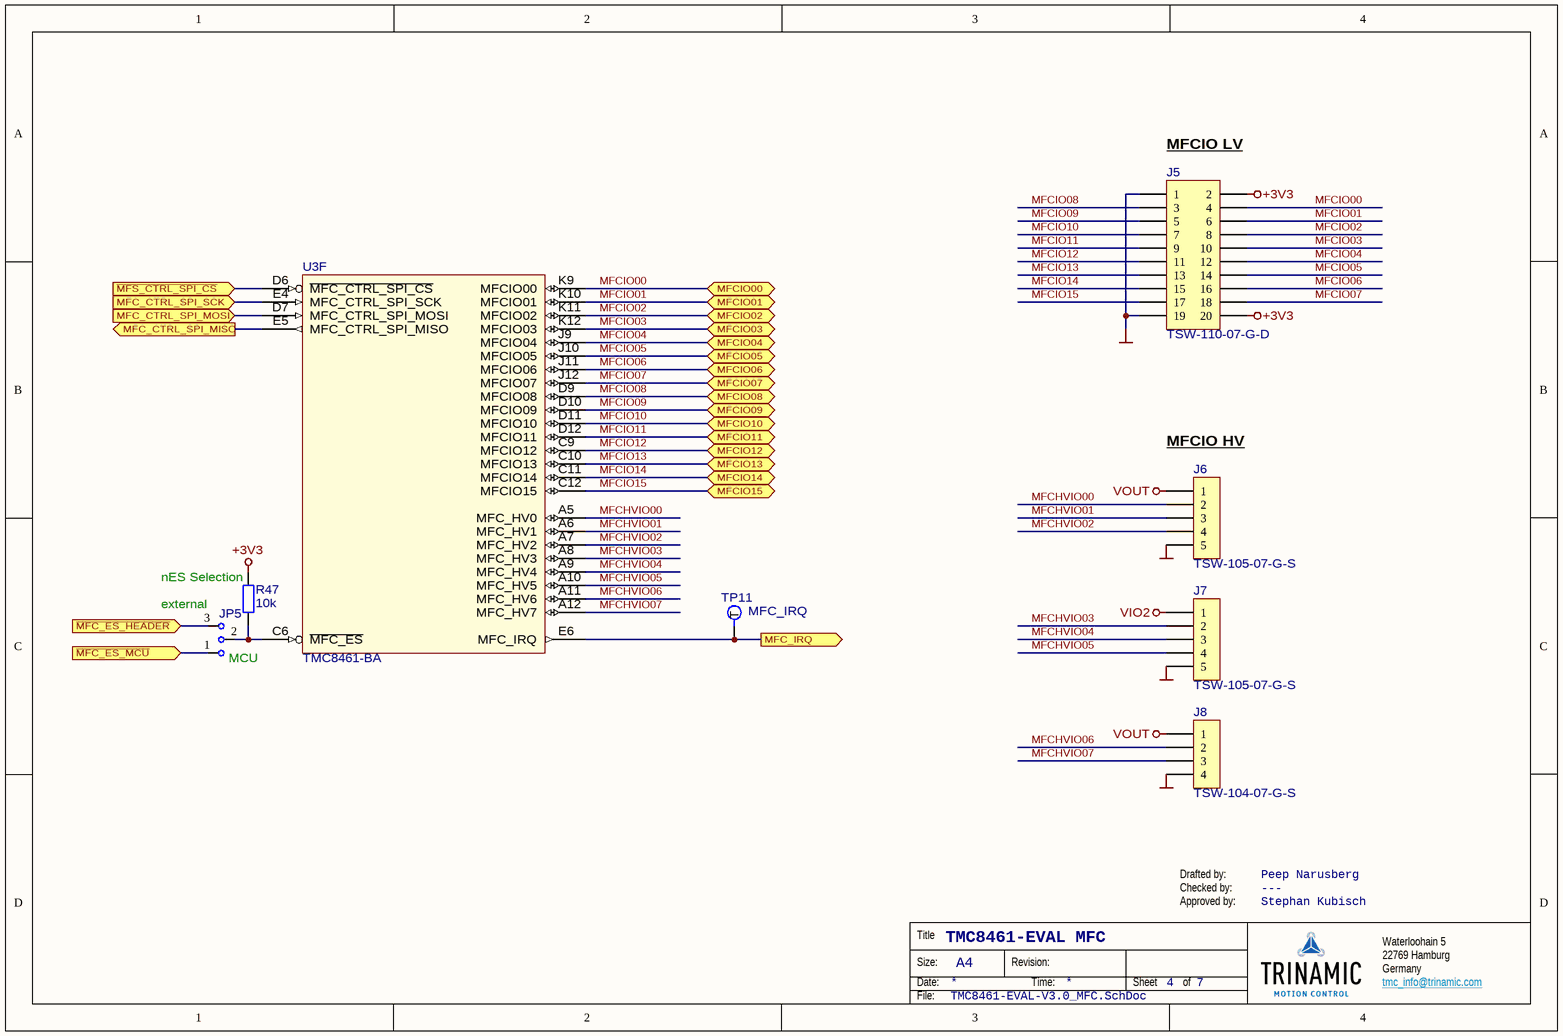
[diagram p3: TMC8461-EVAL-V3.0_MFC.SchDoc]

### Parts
J5  Part Number: TSW-110-07-G-D  [SAMTEC_TSW-110-07-G-D]  (hidden comment: HDR2x10)
J6  Part Number: TSW-105-07-G-S  [SAMTEC_TSW-105-07-G-S]  (hidden comment: HDR1x5)
J7  Part Number: TSW-105-07-G-S  [SAMTEC_TSW-105-07-G-S]  (hidden comment: HDR1x5)
J8  Part Number: TSW-104-07-G-S  [SAMTEC_TSW-104-07-G-S]  (hidden comment: HDR1x4)
JP5  JUMPER1X3A  [SAMTEC_TSW-103-07-G-S]  (value not drawn)
R47  value 10k  [RESC1608N]  (hidden comment: RESC)
TP11  MFC_IRQ  [TP100P254]  (no BOM)
U3  50588  [BGA144C80P12X12_1000X1000X100]  (value not drawn)  (part F of 6)

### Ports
MFC_CTRL_SPI_MISO (out), MFC_CTRL_SPI_MOSI (in), MFC_CTRL_SPI_SCK (in), MFC_IRQ (out), MFCIO00 (bidir), MFCIO01 (bidir), MFCIO02 (bidir), MFCIO03 (bidir), MFCIO04 (bidir), MFCIO05 (bidir), MFCIO06 (bidir), MFCIO07 (bidir), MFCIO08 (bidir), MFCIO09 (bidir), MFCIO10 (bidir), MFCIO11 (bidir), MFCIO12 (bidir), MFCIO13 (bidir), MFCIO14 (bidir), MFCIO15 (bidir), ~{MFC_ES_HEADER} (in), ~{MFC_ES_MCU} (in), ~{MFS_CTRL_SPI_CS} (in)

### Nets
+3V3: J5.2 J5.20 R47.2
GND: J5.1 J5.19 J6.5 J7.5 J8.4
VIO2: J7.1
VOUT: J6.1 J8.1
~{MFC_ES_HEADER}: JP5.3(C3) ; port ~{MFC_ES_HEADER}
~{MFC_ES_MCU}: JP5.1(C1) ; port ~{MFC_ES_MCU}
~{MFS_CTRL_SPI_CS}: U3.D6(~{MFC_CTRL_SPI_CS}) ; port ~{MFS_CTRL_SPI_CS}
MFC_CTRL_SPI_MISO: U3.E5(MFC_CTRL_SPI_MISO) ; port MFC_CTRL_SPI_MISO
MFC_CTRL_SPI_MOSI: U3.D7(MFC_CTRL_SPI_MOSI) ; port MFC_CTRL_SPI_MOSI
MFC_CTRL_SPI_SCK: U3.E4(MFC_CTRL_SPI_SCK) ; port MFC_CTRL_SPI_SCK
MFC_IRQ: TP11.1(T) U3.E6(MFC_IRQ) ; port MFC_IRQ
MFCHVIO00: J6.2 U3.A5(MFC_HV0)
MFCHVIO01: J6.3 U3.A6(MFC_HV1)
MFCHVIO02: J6.4 U3.A7(MFC_HV2)
MFCHVIO03: J7.2 U3.A8(MFC_HV3)
MFCHVIO04: J7.3 U3.A9(MFC_HV4)
MFCHVIO05: J7.4 U3.A10(MFC_HV5)
MFCHVIO06: J8.2 U3.A11(MFC_HV6)
MFCHVIO07: J8.3 U3.A12(MFC_HV7)
MFCIO00: J5.4 U3.K9(MFCIO00) ; port MFCIO00
MFCIO01: J5.6 U3.K10(MFCIO01) ; port MFCIO01
MFCIO02: J5.8 U3.K11(MFCIO02) ; port MFCIO02
MFCIO03: J5.10 U3.K12(MFCIO03) ; port MFCIO03
MFCIO04: J5.12 U3.J9(MFCIO04) ; port MFCIO04
MFCIO05: J5.14 U3.J10(MFCIO05) ; port MFCIO05
MFCIO06: J5.16 U3.J11(MFCIO06) ; port MFCIO06
MFCIO07: J5.18 U3.J12(MFCIO07) ; port MFCIO07
MFCIO08: J5.3 U3.D9(MFCIO08) ; port MFCIO08
MFCIO09: J5.5 U3.D10(MFCIO09) ; port MFCIO09
MFCIO10: J5.7 U3.D11(MFCIO10) ; port MFCIO10
MFCIO11: J5.9 U3.D12(MFCIO11) ; port MFCIO11
MFCIO12: J5.11 U3.C9(MFCIO12) ; port MFCIO12
MFCIO13: J5.13 U3.C10(MFCIO13) ; port MFCIO13
MFCIO14: J5.15 U3.C11(MFCIO14) ; port MFCIO14
MFCIO15: J5.17 U3.C12(MFCIO15) ; port MFCIO15
NetJP5_2: JP5.2(C2) R47.1 U3.C6(~{MFC_ES})

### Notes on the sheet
- (near J5) MFCIO LV
- (near J6) MFCIO HV
- (near R47) nES Selection
- (near JP5) external
- (near JP5) MCU
- Drafted by:
- Checked by:
- Approved by:
- Peep Narusberg
- ---
- Stephan Kubisch

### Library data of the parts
J5 = 50583: 2x10 pin connector; Manufacturer: Samtec; Id: 50583
J6 J7 = 50584: 1X5 pin connector; Manufacturer: Samtec; Id: 50584
J8 = 50585: 1X4 pin connector; Manufacturer: Samtec; Id: 50585; Value: 1x5
JP5 = 50570: as JP1 on sheet TMC8461-EVAL-V3.0_Main
R47 = 10028: as R28 on sheet TMC8461-EVAL-V3.0_Control
TP11 = 50094: as TP1 on sheet TMC8461-EVAL-V3.0_Main
U3 = 50588: as U3 on sheet TMC8461-EVAL-V3.0_Power

## Sheet TMC8461-EVAL-V3.0_PHY_IN.SchDoc: PHY IN Port
size A4; CompanyName: Hedgehog OÜ; Revision: V3.0; SheetNumber: 5; SheetTotal: 7; Author: Peep Narusberg; DrawnBy: Peep Narusberg; Engineer: Peep Narusberg; Organization: Hedgehog OÜ; Address1: Waterloohain 5; Address2: 22769 Hamburg; Address3: Germany; Address4: tmc_info@trinamic.com
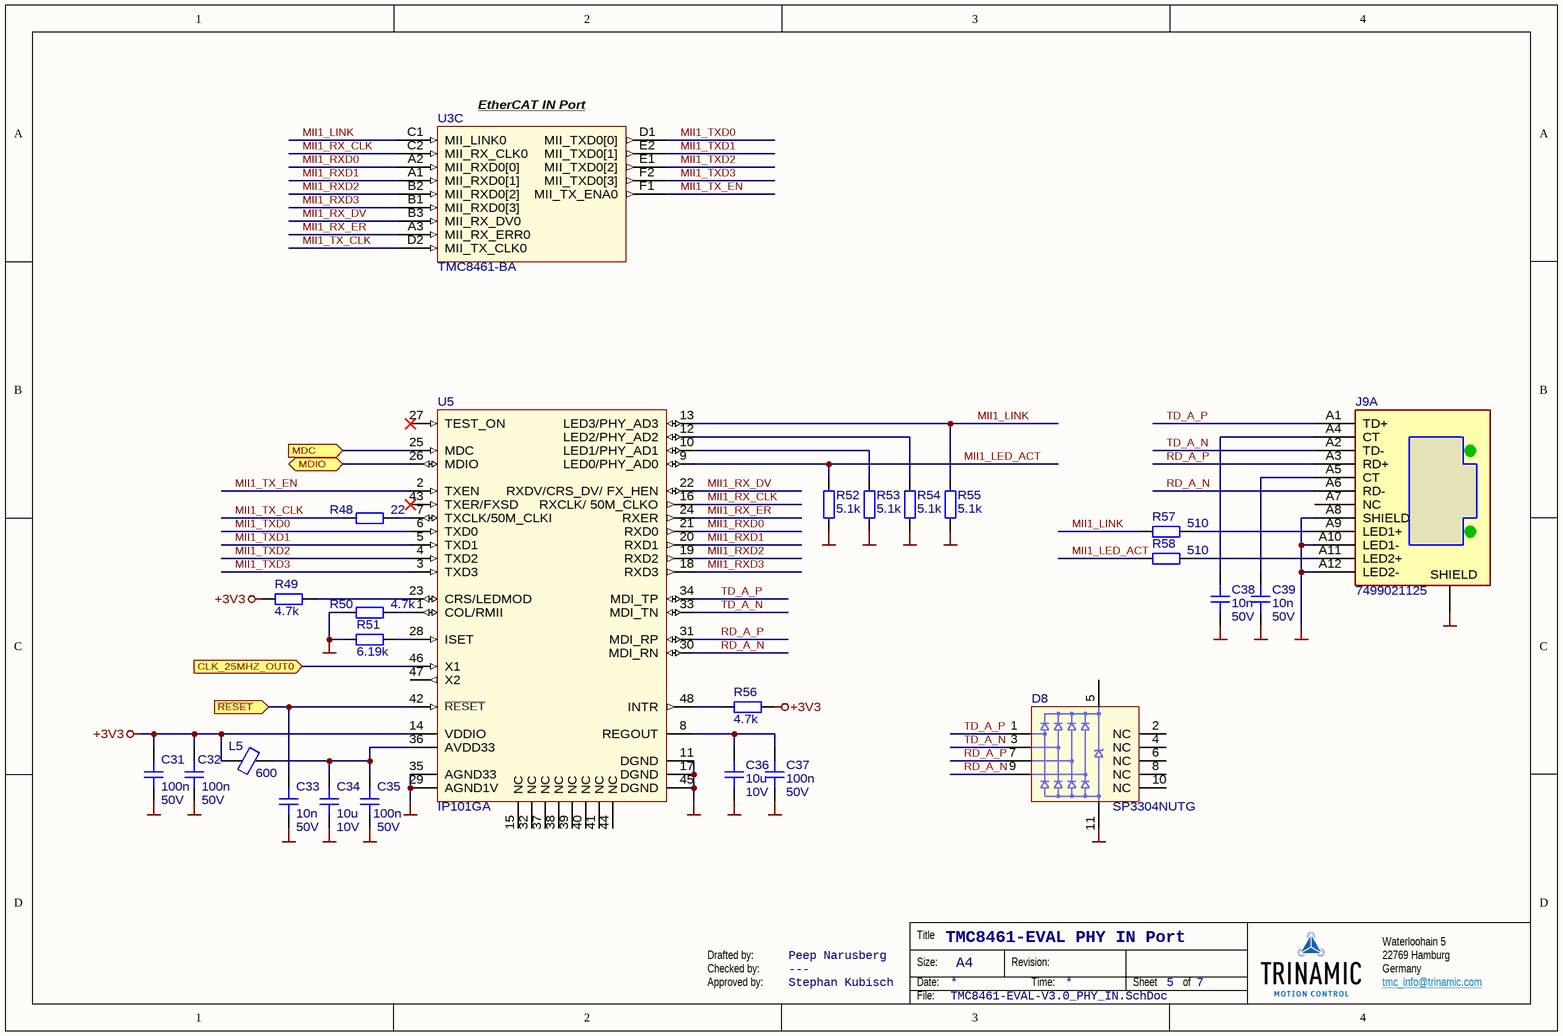
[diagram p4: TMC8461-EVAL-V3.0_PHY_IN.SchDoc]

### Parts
C31  value 100n  Voltage: 50V  [CAPC1608N]  (hidden comment: CAPC)
C32  value 100n  Voltage: 50V  [CAPC1608N]  (hidden comment: CAPC)
C33  value 10n  Voltage: 50V  [CAPC1608N]  (hidden comment: CAPC)
C34  value 10u  Voltage: 10V  [CAPC1608N]  (hidden comment: CAPC)
C35  value 100n  Voltage: 50V  [CAPC1608N]  (hidden comment: CAPC)
C36  value 10u  Voltage: 10V  [CAPC1608N]  (hidden comment: CAPC)
C37  value 100n  Voltage: 50V  [CAPC1608N]  (hidden comment: CAPC)
C38  value 10n  Voltage: 50V  [CAPC1608N]  (hidden comment: CAPC)
C39  value 10n  Voltage: 50V  [CAPC1608N]  (hidden comment: CAPC)
D8  Part Number: SP3304NUTG  [SON50P260X55_HS-11N-LF]  (hidden comment: SP3304N)
J9  Part Number: 7499021125  [WUERTH_7499021125]  (hidden comment: RJMAGX2)  (part A of 2)
L5  value 600  [INDC1608X09N]  (hidden comment: FB)
R48  value 22  [RESC1608N]  (hidden comment: RESC)
R49  value 4.7k  [RESC1608N]  (hidden comment: RESC)
R50  value 4.7k  [RESC1608N]  (hidden comment: RESC)
R51  value 6.19k  [RESC1608N]  (hidden comment: RESC)
R52  value 5.1k  [RESC1608N]  (hidden comment: RESC)
R53  value 5.1k  [RESC1608N]  (hidden comment: RESC)
R54  value 5.1k  [RESC1608N]  (hidden comment: RESC)
R55  value 5.1k  [RESC1608N]  (hidden comment: RESC)
R56  value 4.7k  [RESC1608N]  (hidden comment: RESC)
R57  value 510  [RESC1608N]  (hidden comment: RESC)
R58  value 510  [RESC1608N]  (hidden comment: RESC)
U3  50588  [BGA144C80P12X12_1000X1000X100]  (value not drawn)  (part C of 6)
U5  IP101GA  [TSQFP50P900X900X160-48N]

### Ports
CLK_25MHZ_OUT0 (in), MDC (in), MDIO (bidir), ~{RESET} (in)

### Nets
+3V3: C31.2 C32.2 L5.1 R49.1 R56.2 U5.14(VDDIO)
GND: C31.1 C32.1 C33.1 C34.1 C35.1 C36.1 C37.1 C38.1 C39.1 D8.11(-) J9.A8(SHIELD) J9.A10(LED1-) J9.A12(LED2-) J9.Shield R50.1 R51.1 R52.1 R53.1 R54.1 R55.1 U5.11(DGND) U5.17(DGND) U5.29(AGND1V) U5.35(AGND33) U5.45(DGND)
CLK_25MHZ_OUT0: U5.46(X1) ; port CLK_25MHZ_OUT0
MDC: U5.25(MDC) ; port MDC
MDIO: U5.26(MDIO) ; port MDIO
MII1_LED_ACT: R52.2 R58.1 U5.9(LED0/PHY_AD0)
MII1_LINK: R55.2 R57.1 U3.C1(MII_LINK0) U5.13(LED3/PHY_AD3)
MII1_RX_CLK: U3.C2(MII_RX_CLK0) U5.16(RXCLK/_50M_CLKO)
MII1_RX_DV: U3.B3(MII_RX_DV0) U5.22(RXDV/CRS_DV/_FX_HEN)
MII1_RX_ER: U3.A3(MII_RX_ERR0) U5.24(RXER)
MII1_RXD0: U3.A2(MII_RXD0[0]) U5.21(RXD0)
MII1_RXD1: U3.A1(MII_RXD0[1]) U5.20(RXD1)
MII1_RXD2: U3.B2(MII_RXD0[2]) U5.19(RXD2)
MII1_RXD3: U3.B1(MII_RXD0[3]) U5.18(RXD3)
MII1_TX_CLK: R48.1 U3.D2(MII_TX_CLK0)
MII1_TX_EN: U3.F1(MII_TX_ENA0) U5.2(TXEN)
MII1_TXD0: U3.D1(MII_TXD0[0]) U5.6(TXD0)
MII1_TXD1: U3.E2(MII_TXD0[1]) U5.5(TXD1)
MII1_TXD2: U3.E1(MII_TXD0[2]) U5.4(TXD2)
MII1_TXD3: U3.F2(MII_TXD0[3]) U5.3(TXD3)
~{RESET}: C33.2 U5.42(~{RESET}) ; port ~{RESET}
RD_A_N: D8.9 J9.A6(RD-) U5.30(MDI_RN)
RD_A_P: D8.7 J9.A3(RD+) U5.31(MDI_RP)
TD_A_N: D8.3 J9.A2(TD-) U5.33(MDI_TN)
TD_A_P: D8.1 J9.A1(TD+) U5.34(MDI_TP)
NetC34_2: C34.2 C35.2 L5.2 U5.36(AVDD33)
NetC36_2: C36.2 C37.2 U5.8(REGOUT)
NetC38_2: C38.2 J9.A4(CT)
NetC39_2: C39.2 J9.A5(CT)
NetJ9_A9: J9.A9(LED1+) R57.2
NetJ9_A11: J9.A11(LED2+) R58.2
NetR48_2: R48.2 U5.7(TXCLK/50M_CLKI)
NetR49_2: R49.2 U5.23(CRS/LEDMOD)
NetR50_2: R50.2 U5.1(COL/RMII)
NetR51_2: R51.2 U5.28(ISET)
NetR53_2: R53.2 U5.10(LED1/PHY_AD1)
NetR54_2: R54.2 U5.12(LED2/PHY_AD2)
NetR56_1: R56.1 U5.48(INTR)

Not connected (* = marked no-connect by the designer): D8 2(NC) 4(NC) 5 6(NC) 8(NC) 10(NC); J9 A7(NC); U5 15(NC) 27(TEST_ON)* 32(NC) 37(NC) 38(NC) 39(NC) 40(NC) 41(NC) 43(TXER/FXSD)* 44(NC) 47(X2)

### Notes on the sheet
- Drafted by:
- Checked by:
- Approved by:
- Peep Narusberg
- ---
- Stephan Kubisch

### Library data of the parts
C31 C32 C35 C37 = 20027: as C5 on sheet TMC8461-EVAL-V3.0_Power
C33 C38 C39 = 20038: as C29 on sheet TMC8461-EVAL-V3.0_Control
C34 C36 = 20111: as C3 on sheet TMC8461-EVAL-V3.0_Main
D8 = 50693: TVS Diode Array; Manufacturer: Littelfuse; Id: 50693; Value: 4xETH,300W
J9 = 50579: Dual LAN-Transformer WE-RJ45LAN 10/100BaseT; Manufacturer: Wuerth; Id: 50579; Value: 2xRJ45MAG
L5 = 60036: as L1 on sheet TMC8461-EVAL-V3.0_Power
R48 = 10034: as R34 on sheet TMC8461-EVAL-V3.0_Control
R49 R50 R56 = 10032: as R24 on sheet TMC8461-EVAL-V3.0_Power
R51 = 10168: Chip Resistor; Manufacturer: Any; Part Number: 6.19k, 1%, 100mW, 0603 (1608 metric) chip resistor; Id: 10168; Power: 100mW; Tolerance: 1%
R52-R55 = 10167: Chip Resistor; Manufacturer: Any; Part Number: 5.1k, 1%, 100mW, 0603 (1608 metric) chip resistor; Id: 10167; Power: 100mW; Tolerance: 1%
R57 R58 = 10166: Chip Resistor; Manufacturer: Any; Part Number: 510, 1%, 100mW, 0603 (1608 metric) chip resistor; Id: 10166; Power: 100mW; Tolerance: 1%
U3 = 50588: as U3 on sheet TMC8461-EVAL-V3.0_Power
U5 = 50580: Single Port 10/100 MII/RMII/TP/Fiber  Fast Ethernet Transceiver; Manufacturer: ICplus; Id: 50580

## Sheet TMC8461-EVAL-V3.0_PHY_OUT.SchDoc: PHY Out Port
size A4; CompanyName: Hedgehog OÜ; Revision: V3.0; SheetNumber: 6; SheetTotal: 7; Author: Peep Narusberg; DrawnBy: Peep Narusberg; Engineer: Peep Narusberg; Organization: Hedgehog OÜ; Address1: Waterloohain 5; Address2: 22769 Hamburg; Address3: Germany; Address4: tmc_info@trinamic.com
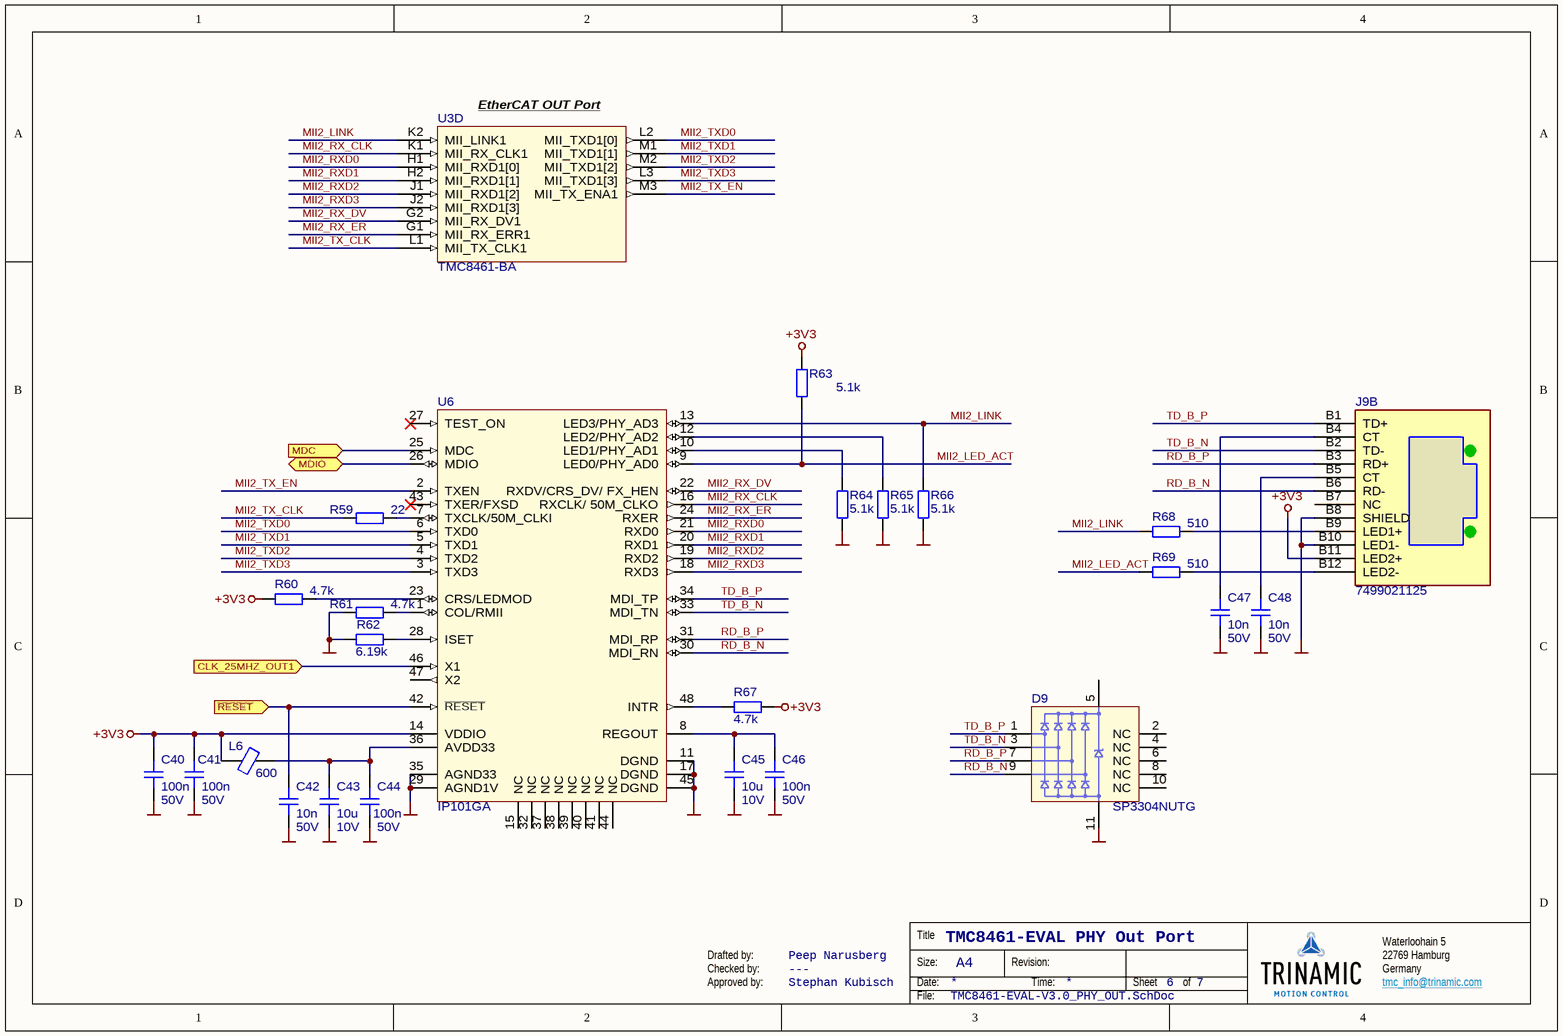
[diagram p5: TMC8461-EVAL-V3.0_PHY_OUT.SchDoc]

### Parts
C40  value 100n  Voltage: 50V  [CAPC1608N]  (hidden comment: CAPC)
C41  value 100n  Voltage: 50V  [CAPC1608N]  (hidden comment: CAPC)
C42  value 10n  Voltage: 50V  [CAPC1608N]  (hidden comment: CAPC)
C43  value 10u  Voltage: 10V  [CAPC1608N]  (hidden comment: CAPC)
C44  value 100n  Voltage: 50V  [CAPC1608N]  (hidden comment: CAPC)
C45  value 10u  Voltage: 10V  [CAPC1608N]  (hidden comment: CAPC)
C46  value 100n  Voltage: 50V  [CAPC1608N]  (hidden comment: CAPC)
C47  value 10n  Voltage: 50V  [CAPC1608N]  (hidden comment: CAPC)
C48  value 10n  Voltage: 50V  [CAPC1608N]  (hidden comment: CAPC)
D9  Part Number: SP3304NUTG  [SON50P260X55_HS-11N-LF]  (hidden comment: SP3304N)
J9  Part Number: 7499021125  [WUERTH_7499021125]  (hidden comment: RJMAGX2)  (part B of 2)
L6  value 600  [INDC1608X09N]  (hidden comment: FB)
R59  value 22  [RESC1608N]  (hidden comment: RESC)
R60  value 4.7k  [RESC1608N]  (hidden comment: RESC)
R61  value 4.7k  [RESC1608N]  (hidden comment: RESC)
R62  value 6.19k  [RESC1608N]  (hidden comment: RESC)
R63  value 5.1k  [RESC1608N]  (hidden comment: RESC)
R64  value 5.1k  [RESC1608N]  (hidden comment: RESC)
R65  value 5.1k  [RESC1608N]  (hidden comment: RESC)
R66  value 5.1k  [RESC1608N]  (hidden comment: RESC)
R67  value 4.7k  [RESC1608N]  (hidden comment: RESC)
R68  value 510  [RESC1608N]  (hidden comment: RESC)
R69  value 510  [RESC1608N]  (hidden comment: RESC)
U3  50588  [BGA144C80P12X12_1000X1000X100]  (value not drawn)  (part D of 6)
U6  IP101GA  [TSQFP50P900X900X160-48N]

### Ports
CLK_25MHZ_OUT1 (in), MDC (in), MDIO (bidir), ~{RESET} (in)

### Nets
+3V3: C40.2 C41.2 J9.B11(LED2+) L6.1 R60.1 R63.2 R67.2 U6.14(VDDIO)
GND: C40.1 C41.1 C42.1 C43.1 C44.1 C45.1 C46.1 C47.1 C48.1 D9.11(-) J9.B8(SHIELD) J9.B10(LED1-) R61.1 R62.1 R64.1 R65.1 R66.1 U6.11(DGND) U6.17(DGND) U6.29(AGND1V) U6.35(AGND33) U6.45(DGND)
CLK_25MHZ_OUT1: U6.46(X1) ; port CLK_25MHZ_OUT1
MDC: U6.25(MDC) ; port MDC
MDIO: U6.26(MDIO) ; port MDIO
MII2_LED_ACT: R63.1 R69.1 U6.9(LED0/PHY_AD0)
MII2_LINK: R66.2 R68.1 U3.K2(MII_LINK1) U6.13(LED3/PHY_AD3)
MII2_RX_CLK: U3.K1(MII_RX_CLK1) U6.16(RXCLK/_50M_CLKO)
MII2_RX_DV: U3.G2(MII_RX_DV1) U6.22(RXDV/CRS_DV/_FX_HEN)
MII2_RX_ER: U3.G1(MII_RX_ERR1) U6.24(RXER)
MII2_RXD0: U3.H1(MII_RXD1[0]) U6.21(RXD0)
MII2_RXD1: U3.H2(MII_RXD1[1]) U6.20(RXD1)
MII2_RXD2: U3.J1(MII_RXD1[2]) U6.19(RXD2)
MII2_RXD3: U3.J2(MII_RXD1[3]) U6.18(RXD3)
MII2_TX_CLK: R59.1 U3.L1(MII_TX_CLK1)
MII2_TX_EN: U3.M3(MII_TX_ENA1) U6.2(TXEN)
MII2_TXD0: U3.L2(MII_TXD1[0]) U6.6(TXD0)
MII2_TXD1: U3.M1(MII_TXD1[1]) U6.5(TXD1)
MII2_TXD2: U3.M2(MII_TXD1[2]) U6.4(TXD2)
MII2_TXD3: U3.L3(MII_TXD1[3]) U6.3(TXD3)
~{RESET}: C42.2 U6.42(~{RESET}) ; port ~{RESET}
RD_B_N: D9.9 J9.B6(RD-) U6.30(MDI_RN)
RD_B_P: D9.7 J9.B3(RD+) U6.31(MDI_RP)
TD_B_N: D9.3 J9.B2(TD-) U6.33(MDI_TN)
TD_B_P: D9.1 J9.B1(TD+) U6.34(MDI_TP)
NetC43_2: C43.2 C44.2 L6.2 U6.36(AVDD33)
NetC45_2: C45.2 C46.2 U6.8(REGOUT)
NetC47_2: C47.2 J9.B4(CT)
NetC48_2: C48.2 J9.B5(CT)
NetJ9_B9: J9.B9(LED1+) R68.2
NetJ9_B12: J9.B12(LED2-) R69.2
NetR59_2: R59.2 U6.7(TXCLK/50M_CLKI)
NetR60_2: R60.2 U6.23(CRS/LEDMOD)
NetR61_2: R61.2 U6.1(COL/RMII)
NetR62_2: R62.2 U6.28(ISET)
NetR64_2: R64.2 U6.10(LED1/PHY_AD1)
NetR65_2: R65.2 U6.12(LED2/PHY_AD2)
NetR67_1: R67.1 U6.48(INTR)

Not connected (* = marked no-connect by the designer): D9 2(NC) 4(NC) 5 6(NC) 8(NC) 10(NC); J9 B7(NC); U6 15(NC) 27(TEST_ON)* 32(NC) 37(NC) 38(NC) 39(NC) 40(NC) 41(NC) 43(TXER/FXSD)* 44(NC) 47(X2)

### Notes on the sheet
- Drafted by:
- Checked by:
- Approved by:
- Peep Narusberg
- ---
- Stephan Kubisch

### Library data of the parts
C40 C41 C44 C46 = 20027: as C5 on sheet TMC8461-EVAL-V3.0_Power
C42 C47 C48 = 20038: as C29 on sheet TMC8461-EVAL-V3.0_Control
C43 C45 = 20111: as C3 on sheet TMC8461-EVAL-V3.0_Main
D9 = 50693: as D8 on sheet TMC8461-EVAL-V3.0_PHY_IN
J9 = 50579: as J9 on sheet TMC8461-EVAL-V3.0_PHY_IN
L6 = 60036: as L1 on sheet TMC8461-EVAL-V3.0_Power
R59 = 10034: as R34 on sheet TMC8461-EVAL-V3.0_Control
R60 R61 R67 = 10032: as R24 on sheet TMC8461-EVAL-V3.0_Power
R62 = 10168: as R51 on sheet TMC8461-EVAL-V3.0_PHY_IN
R63-R66 = 10167: as R52 on sheet TMC8461-EVAL-V3.0_PHY_IN
R68 R69 = 10166: as R57 on sheet TMC8461-EVAL-V3.0_PHY_IN
U3 = 50588: as U3 on sheet TMC8461-EVAL-V3.0_Power
U6 = 50580: as U5 on sheet TMC8461-EVAL-V3.0_PHY_IN

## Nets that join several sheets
+3V3: TMC8461-EVAL-V3.0_Main (5 pins), TMC8461-EVAL-V3.0_Power (19 pins), TMC8461-EVAL-V3.0_Control (18 pins), TMC8461-EVAL-V3.0_MFC (J5.2 J5.20 R47.2), TMC8461-EVAL-V3.0_PHY_IN (6 pins), TMC8461-EVAL-V3.0_PHY_OUT (8 pins)
+5V_REG: TMC8461-EVAL-V3.0_Main (5 pins), TMC8461-EVAL-V3.0_Control (J4.14)
GND: TMC8461-EVAL-V3.0_Main (22 pins), TMC8461-EVAL-V3.0_Power (44 pins), TMC8461-EVAL-V3.0_Control (28 pins), TMC8461-EVAL-V3.0_MFC (5 pins), TMC8461-EVAL-V3.0_PHY_IN (25 pins), TMC8461-EVAL-V3.0_PHY_OUT (22 pins)
VDD1V8: TMC8461-EVAL-V3.0_Main (TP6.1), TMC8461-EVAL-V3.0_Power (9 pins)
VIO2: TMC8461-EVAL-V3.0_Main (JP1.2 TP5.1), TMC8461-EVAL-V3.0_Power (C21.2 U3.B8), TMC8461-EVAL-V3.0_MFC (J7.1)
VOUT: TMC8461-EVAL-V3.0_Main (JP1.3 TP4.1), TMC8461-EVAL-V3.0_Power (10 pins), TMC8461-EVAL-V3.0_MFC (J6.1 J8.1)
VS: TMC8461-EVAL-V3.0_Main (6 pins), TMC8461-EVAL-V3.0_Power (6 pins)
~{SPI1_CS}: TMC8461-EVAL-V3.0_Main (J2.30), TMC8461-EVAL-V3.0_Control (U3.M5)
CLK_16MHZ_OUT: TMC8461-EVAL-V3.0_Main (J3.23), TMC8461-EVAL-V3.0_Control (J4.13 U3.H8)
CLK_25MHZ_OUT0: TMC8461-EVAL-V3.0_Control (U3.E3), TMC8461-EVAL-V3.0_PHY_IN (U5.46)
CLK_25MHZ_OUT1: TMC8461-EVAL-V3.0_Control (U3.H3), TMC8461-EVAL-V3.0_PHY_OUT (U6.46)
EEPROM_OK: TMC8461-EVAL-V3.0_Main (J2.38), TMC8461-EVAL-V3.0_Control (U3.J7)
EN_16MHZ_OUT: TMC8461-EVAL-V3.0_Main (J2.19), TMC8461-EVAL-V3.0_Control (U3.G10)
~{MFC_ES_HEADER}: TMC8461-EVAL-V3.0_Control (J4.8), TMC8461-EVAL-V3.0_MFC (JP5.3)
~{MFC_ES_MCU}: TMC8461-EVAL-V3.0_Main (J2.23), TMC8461-EVAL-V3.0_MFC (JP5.1)
~{MFS_CTRL_SPI_CS}: TMC8461-EVAL-V3.0_Main (J2.24), TMC8461-EVAL-V3.0_MFC (U3.D6)
MDC: TMC8461-EVAL-V3.0_Control (U3.F3), TMC8461-EVAL-V3.0_PHY_IN (U5.25), TMC8461-EVAL-V3.0_PHY_OUT (U6.25)
MDIO: TMC8461-EVAL-V3.0_Control (R44.1 U3.G3), TMC8461-EVAL-V3.0_PHY_IN (U5.26), TMC8461-EVAL-V3.0_PHY_OUT (U6.26)
MFC_CTRL_SPI_MISO: TMC8461-EVAL-V3.0_Main (J2.28), TMC8461-EVAL-V3.0_MFC (U3.E5)
MFC_CTRL_SPI_MOSI: TMC8461-EVAL-V3.0_Main (J2.29), TMC8461-EVAL-V3.0_MFC (U3.D7)
MFC_CTRL_SPI_SCK: TMC8461-EVAL-V3.0_Main (J2.27), TMC8461-EVAL-V3.0_MFC (U3.E4)
MFC_IRQ: TMC8461-EVAL-V3.0_Main (J2.25), TMC8461-EVAL-V3.0_MFC (TP11.1 U3.E6)
MFCIO00: TMC8461-EVAL-V3.0_Main (R6.1), TMC8461-EVAL-V3.0_MFC (J5.4 U3.K9)
MFCIO01: TMC8461-EVAL-V3.0_Main (R5.1), TMC8461-EVAL-V3.0_MFC (J5.6 U3.K10)
MFCIO02: TMC8461-EVAL-V3.0_Main (R4.1), TMC8461-EVAL-V3.0_MFC (J5.8 U3.K11)
MFCIO03: TMC8461-EVAL-V3.0_Main (R3.1), TMC8461-EVAL-V3.0_MFC (J5.10 U3.K12)
MFCIO04: TMC8461-EVAL-V3.0_Main (R2.1 R14.1), TMC8461-EVAL-V3.0_MFC (J5.12 U3.J9)
MFCIO05: TMC8461-EVAL-V3.0_Main (R1.1 R15.1), TMC8461-EVAL-V3.0_MFC (J5.14 U3.J10)
MFCIO06: TMC8461-EVAL-V3.0_Main (R13.1), TMC8461-EVAL-V3.0_MFC (J5.16 U3.J11)
MFCIO07: TMC8461-EVAL-V3.0_Main (R12.1 R16.1), TMC8461-EVAL-V3.0_MFC (J5.18 U3.J12)
MFCIO08: TMC8461-EVAL-V3.0_Main (R11.1 R17.1), TMC8461-EVAL-V3.0_MFC (J5.3 U3.D9)
MFCIO09: TMC8461-EVAL-V3.0_Main (R10.1 R18.1), TMC8461-EVAL-V3.0_MFC (J5.5 U3.D10)
MFCIO10: TMC8461-EVAL-V3.0_Main (R9.1), TMC8461-EVAL-V3.0_MFC (J5.7 U3.D11)
MFCIO11: TMC8461-EVAL-V3.0_Main (R8.1), TMC8461-EVAL-V3.0_MFC (J5.9 U3.D12)
MFCIO12: TMC8461-EVAL-V3.0_Main (R7.1), TMC8461-EVAL-V3.0_MFC (J5.11 U3.C9)
MFCIO13: TMC8461-EVAL-V3.0_Main (R19.1), TMC8461-EVAL-V3.0_MFC (J5.13 U3.C10)
MFCIO14: TMC8461-EVAL-V3.0_Main (R20.1), TMC8461-EVAL-V3.0_MFC (J5.15 U3.C11)
MFCIO15: TMC8461-EVAL-V3.0_Main (R21.1), TMC8461-EVAL-V3.0_MFC (J5.17 U3.C12)
PDI_EOF: TMC8461-EVAL-V3.0_Main (J2.35), TMC8461-EVAL-V3.0_Control (J4.11 U3.K4)
PDI_SOF: TMC8461-EVAL-V3.0_Main (J2.34), TMC8461-EVAL-V3.0_Control (J4.9 U3.L4)
PDI_SPI_IRQ: TMC8461-EVAL-V3.0_Main (J2.26), TMC8461-EVAL-V3.0_Control (U3.K5)
PDI_WD_STATE: TMC8461-EVAL-V3.0_Main (J2.37), TMC8461-EVAL-V3.0_Control (U3.H7)
PDI_WD_TRIGGER: TMC8461-EVAL-V3.0_Main (J2.36), TMC8461-EVAL-V3.0_Control (U3.H6)
PROM_CLK: TMC8461-EVAL-V3.0_Main (J2.10), TMC8461-EVAL-V3.0_Control (R45.1 U3.J5 U4.6)
PROM_DATA: TMC8461-EVAL-V3.0_Main (J2.11), TMC8461-EVAL-V3.0_Control (R46.1 U3.J6 U4.5)
~{RESET}: TMC8461-EVAL-V3.0_Control (C29.2 R34.2 U3.J8), TMC8461-EVAL-V3.0_PHY_IN (C33.2 U5.42), TMC8461-EVAL-V3.0_PHY_OUT (C42.2 U6.42)
~{RST_EXT}: TMC8461-EVAL-V3.0_Main (J2.41), TMC8461-EVAL-V3.0_Control (R30.2 R31.2)
SPI1_SCK: TMC8461-EVAL-V3.0_Main (J2.31 U2.6), TMC8461-EVAL-V3.0_Control (U3.L5)
SPI1_SDI: TMC8461-EVAL-V3.0_Main (J2.32 U2.2), TMC8461-EVAL-V3.0_Control (U3.M6)
SPI1_SDO: TMC8461-EVAL-V3.0_Main (J2.33 U2.5), TMC8461-EVAL-V3.0_Control (U3.L6)
SYNC_OUT0: TMC8461-EVAL-V3.0_Main (J2.39), TMC8461-EVAL-V3.0_Control (J4.1 U3.D8)
SYNC_OUT1: TMC8461-EVAL-V3.0_Main (J2.40), TMC8461-EVAL-V3.0_Control (J4.3 U3.E8)

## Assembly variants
Initial: all parts fitted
